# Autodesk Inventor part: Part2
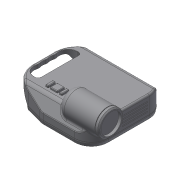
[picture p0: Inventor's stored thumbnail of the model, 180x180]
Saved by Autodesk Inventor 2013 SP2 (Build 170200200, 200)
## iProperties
Created: 2013-06
Part Number: Part2
Material: 一般
Document SubType Name: Modeling
Designer: 3214325
Density: 1 g/cm^3
Author: 3214325
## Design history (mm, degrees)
sketch "Sketch1"
  geometry: L1 (66, -150)-(-66, -150); L2 (-66, -150)-(-66, 0); L3 (-66, 0)-(66, 0); L4 (66, 0)-(66, -150); L5 (92.4, 0)-(-92.4, 0) reference; L6 (0, -180)-(0, 30) reference; 1 further point
  constraints: 8 end point, 2 parallel, 1 collinear, 1 horizontal, 1 perpendicular, 1 other
  dimensions: "d0" = 132 distance of L2.end L3.end; "d1" = 150 distance of L1.end L2.end
extrude "Extrusion1" new body sketch "Sketch1" distance "d2" = 2; taper "d3" = 0 deg
sketch "Sketch2"
  geometry: L1 (66, -150)-(-66, -150) reference; L2 (66, 0)-(66, -150) reference; L3 (-66, 0)-(66, 0) reference; L4 (-66, -150)-(-66, 0) reference; L5 (92.4, 0)-(-92.4, 0) reference; L6 (-66, -88)-(-49.387, -150); L7 (0, -180)-(0, 30) reference; L8 (66, -88)-(49.387, -150); L9 (-66, -88)-(-66, -150); L10 (-66, -150)-(-49.387, -150); L11 (49.387, -150)-(66, -150); L12 (66, -150)-(66, -88); 1 further point
  constraints: 12 end point, 4 point on line, 2 horizontal, 2 vertical
  dimensions: "d4" = 88 distance from line of L6.start L5; "d5" = 15 deg angle of L6 L4; "d7" = 88 distance from line of L8.start L5; "d8" = 15 deg angle of L8 L2
extrude "Extrusion2" cut sketch "Sketch2" distance "d9" = 2; taper "d10" = 0 deg
fillet "Fillet1" dims "d11" = 30
fillet "Fillet2" dims "d12" = 30
fillet "Fillet3" dims "d13" = 40
sketch "Sketch3"
  geometry: L1 (-18.694, -150)-(18.694, -150) reference; L2 (57.331, -120.353)-(64.978, -91.815) reference; L3 (66, -84.05)-(66, -30) reference; L4 (36, 0)-(-36, 0) reference; L5 (-66, -30)-(-66, -84.05) reference; L6 (-64.978, -91.815)-(-57.331, -120.353) reference; A1 r 40 centre (-18.694, -110) between (-57.331, -120.353) and (-18.694, -150) reference; A2 r 40 centre (18.694, -110) between (18.694, -150) and (57.331, -120.353) reference; A3 r 30 centre (36, -84.05) between (64.978, -91.815) and (66, -84.05) reference; A4 r 30 centre (36, -30) between (66, -30) and (36, 0) reference; A5 r 30 centre (-36, -30) between (-36, 0) and (-66, -30) reference; A6 r 30 centre (-36, -84.05) between (-66, -84.05) and (-64.978, -91.815) reference; 1 further point
extrude "Extrusion3" join sketch "Sketch3" distance "d14" = 5; taper "d15" = -10 deg
sketch "Sketch4"
  geometry: L1 (-18.694, 150)-(18.694, 150) reference; L2 (-27, 145)-(27, 145); L3 (33, 139)-(33, 128); L4 (27, 122)-(-27, 122); L5 (-33, 128)-(-33, 139); L6 (0, 180)-(0, -30) reference; A1 r 6 centre (-27, 139) between (-27, 145) and (-33, 139); A2 r 6 centre (-27, 128) between (-33, 128) and (-27, 122); A3 r 6 centre (27, 128) between (27, 122) and (33, 128); A4 r 6 centre (27, 139) between (33, 139) and (27, 145); 4 further points
  constraints: 8 end point, 8 point on circle, 8 tangent, 6 point on line, 4 centre point, 3 equal radius, 2 parallel, 1 horizontal, 1 perpendicular, 1 other
  dimensions: "d16" = 66 distance of point (33, 122) point (-33, 122); "d17" = 23 distance of point (33, 145) point (33, 122); "d18" = 5 distance between parallel lines of L2 L1; "d19" = 6 radius of A1
extrude "Extrusion4" cut sketch "Sketch4" distance "d20" = 15; taper "d21" = 0 deg
sketch "Sketch5"
  geometry: L1 (-33, 128)-(-33, 139) reference; L2 (-27, 145)-(27, 145) reference; L3 (33, 139)-(33, 128) reference; L4 (27, 122)-(-27, 122) reference; L5 (-57.331, 120.353)-(-64.978, 91.815) reference; L6 (-66, 30)-(-66, 84.05) reference; L7 (36, 0)-(-36, 0) reference; L8 (66, 84.05)-(66, 30) reference; L9 (64.978, 91.815)-(57.331, 120.353) reference; L10 (-18.694, 150)-(18.694, 150) reference; L11 (56.365, 120.094)-(64.012, 91.556); L12 (65, 84.05)-(65, 30); L13 (36, 1)-(-36, 1); L14 (-65, 30)-(-65, 84.05); L15 (-64.012, 91.556)-(-56.365, 120.094); L16 (-18.694, 149)-(18.694, 149); A1 r 6 centre (-27, 128) between (-33, 128) and (-27, 122) reference; A2 r 6 centre (-27, 139) between (-27, 145) and (-33, 139) reference; A3 r 6 centre (27, 139) between (33, 139) and (27, 145) reference; A4 r 6 centre (27, 128) between (27, 122) and (33, 128) reference; A5 r 40 centre (-18.694, 110) between (-18.694, 150) and (-57.331, 120.353) reference; A6 r 30 centre (-36, 84.05) between (-64.978, 91.815) and (-66, 84.05) reference; A7 r 30 centre (-36, 30) between (-66, 30) and (-36, 0) reference; A8 r 30 centre (36, 30) between (36, 0) and (66, 30) reference; A9 r 30 centre (36, 84.05) between (66, 84.05) and (64.978, 91.815) reference; A10 r 40 centre (18.694, 110) between (57.331, 120.353) and (18.694, 150) reference; A11 r 39 centre (18.694, 110) between (56.365, 120.094) and (18.694, 149); A12 r 29 centre (36, 84.05) between (65, 84.05) and (64.012, 91.556); A13 r 29 centre (36, 30) between (36, 1) and (65, 30); A14 r 29 centre (-36, 30) between (-65, 30) and (-36, 1); A15 r 29 centre (-36, 84.05) between (-64.012, 91.556) and (-65, 84.05); A16 r 39 centre (-18.694, 110) between (-18.694, 149) and (-56.365, 120.094); 1 further point
  constraints: 12 end point, 12 point on circle, 6 centre point, 11 other
  dimensions: "d28" = 1 distance between parallel lines of L8 L12
extrude "Extrusion5" join sketch "Sketch5" distance "d22" = 0.3; taper "d23" = 0 deg
sketch "Sketch6"
  geometry: L1 (-33, 128)-(-33, 139) reference; L2 (-27, 145)-(27, 145) reference; L3 (33, 139)-(33, 128) reference; L4 (27, 122)-(-27, 122) reference; L5 (18.694, 149)-(-18.694, 149) reference; L6 (-56.365, 120.094)-(-64.012, 91.556) reference; L7 (-65, 84.05)-(-65, 30) reference; L8 (-36, 1)-(36, 1) reference; L9 (65, 30)-(65, 84.05) reference; L10 (64.012, 91.556)-(56.365, 120.094) reference; L11 (0, 206.201)-(0, -40.207) reference; L12 (-99.409, 0)-(99.409, 0) reference; L13 (-39, 171)-(39, 171); L14 (39, 171)-(39, 121); L15 (39, 121)-(-39, 121); L16 (-39, 121)-(-39, 171); A1 r 6 centre (-27, 139) between (-27, 145) and (-33, 139) reference; A2 r 6 centre (27, 139) between (33, 139) and (27, 145) reference; A3 r 6 centre (27, 128) between (27, 122) and (33, 128) reference; A4 r 6 centre (-27, 128) between (-33, 128) and (-27, 122) reference; A5 r 39 centre (18.694, 110) between (56.365, 120.094) and (18.694, 149) reference; A6 r 39 centre (-18.694, 110) between (-18.694, 149) and (-56.365, 120.094) reference; A7 r 29 centre (-36, 84.05) between (-64.012, 91.556) and (-65, 84.05) reference; A8 r 29 centre (-36, 30) between (-65, 30) and (-36, 1) reference; A9 r 29 centre (36, 30) between (36, 1) and (65, 30) reference; A10 r 29 centre (36, 84.05) between (65, 84.05) and (64.012, 91.556) reference
  constraints: 8 end point, 2 parallel, 1 horizontal, 1 perpendicular, 1 other
  dimensions: "d29" = 78 distance of L14.end L15.end; "d30" = 50 distance of L13.end L14.end; "d31" = 121 distance between parallel lines of L12 L15
extrude "Extrusion6" cut sketch "Sketch6" stored distance "d32" = 0.3; taper "d33" = 0 deg
fillet "Fillet4" dims "d34" = 6
fillet "Fillet5" dims "d35" = 2
sketch "Sketch7"
  geometry: L1 (-56.365, 120.094)-(-64.012, 91.556) reference; L2 (-65, 84.05)-(-65, 30) reference; L3 (-36, 1)-(36, 1) reference; L4 (65, 30)-(65, 84.05) reference; L5 (64.012, 91.556)-(56.365, 120.094) reference; L6 (39, 143.297)-(39, 121) reference; L7 (39, 121)-(-39, 121) reference; L8 (-39, 121)-(-39, 143.297) reference; L9 (66, 84.05)-(66, 30); L10 (36, 0)-(-36, 0); L11 (-66, 30)-(-66, 84.05); L12 (-64.978, 91.815)-(-57.331, 120.353); L13 (-38, 139.52)-(-38, 127); L14 (-33, 122)-(33, 122); L15 (38, 127)-(38, 139.52); L16 (57.331, 120.353)-(64.978, 91.815); A1 r 2 centre (-41, 139.52) between (-39, 139.52) and (-42.206, 141.116) reference; A2 r 39 centre (-18.694, 110) between (-39, 143.297) and (-56.365, 120.094) reference; A3 r 29 centre (-36, 84.05) between (-64.012, 91.556) and (-65, 84.05) reference; A4 r 29 centre (-36, 30) between (-65, 30) and (-36, 1) reference; A5 r 29 centre (36, 30) between (36, 1) and (65, 30) reference; A6 r 29 centre (36, 84.05) between (65, 84.05) and (64.012, 91.556) reference; A7 r 39 centre (18.694, 110) between (56.365, 120.094) and (39, 143.297) reference; A8 r 2 centre (41, 139.52) between (42.206, 141.116) and (39, 139.52) reference; A9 r 6 centre (33, 127) between (33, 121) and (39, 127) reference; A10 r 6 centre (-33, 127) between (-39, 127) and (-33, 121) reference; A11 r 30 centre (36, 30) between (36, 0) and (66, 30); A12 r 30 centre (-36, 30) between (-66, 30) and (-36, 0); A13 r 30 centre (-36, 84.05) between (-64.978, 91.815) and (-66, 84.05); A14 r 40 centre (-18.694, 110) between (-42.809, 141.914) and (-57.331, 120.353); A15 r 3 centre (-41, 139.52) between (-38, 139.52) and (-42.809, 141.914); A16 r 5 centre (-33, 127) between (-38, 127) and (-33, 122); A17 r 5 centre (33, 127) between (33, 122) and (38, 127); A18 r 3 centre (41, 139.52) between (42.809, 141.914) and (38, 139.52); A19 r 40 centre (18.694, 110) between (57.331, 120.353) and (42.809, 141.914); A20 r 30 centre (36, 84.05) between (66, 84.05) and (64.978, 91.815); 1 further point
  constraints: 20 point on circle, 16 end point, 10 centre point, 17 other
  dimensions: "d36" = 1 distance between parallel lines of L4 L9
extrude "Extrusion7" join sketch "Sketch7" distance "d37" = 30.7; taper "d38" = 0 deg
sketch "Sketch8"
  geometry: L1 (66, 31)-(64.978, 31) reference; L2 (64.978, 31)-(57.331, 31) reference; L3 (57.331, 31)-(42.809, 31) reference; L4 (42.809, 31)-(38, 31) reference; L5 (38, 31)-(33, 31) reference; L6 (33, 31)-(-33, 31) reference; L7 (-33, 31)-(-38, 31) reference; L8 (-38, 31)-(-42.809, 31) reference; L9 (-42.809, 31)-(-57.331, 31) reference; L10 (-57.331, 31)-(-64.978, 31) reference; L11 (-64.978, 31)-(-66, 31) reference; L12 (-66, 31)-(-36, 31) reference; L13 (-36, 31)-(36, 31) reference; L14 (36, 31)-(66, 31) reference; L15 (-66, 0.3)-(-66, 31) reference; L16 (-66, 0.3)-(-66, 31) reference; L17 (66, 0.3)-(66, 31) reference; L18 (66, 0.3)-(66, 31) reference; L19 (-66, 31)-(-66, 11.006); L20 (-66, 11.006)-(-52, 31); L21 (-52, 31)-(-66, 31); L22 (66, 31)-(66, 11.006); L23 (66, 11.006)-(52, 31); L24 (52, 31)-(66, 31); 1 further point
  constraints: 12 end point, 4 point on line, 2 horizontal
  dimensions: "d39" = 14 distance from line of L20.end L15; "d40" = 14 distance from line of L23.end L17; "d41" = 55 deg angle of L6 L20; "d42" = 55 deg angle of L6 L23
extrude "Extrusion8" cut sketch "Sketch8" distance "d43" = 200; taper "d44" = 0 deg; dims "d52" = 10, "d108" = 1, "d154" = 5, "d193" = 0.5
sketch "Sketch9"
  geometry: L1 (-8.6, 0)-(37.6, 0) reference; L2 (0, -180)-(0, 30) reference; L3 (0, -150)-(-2, -150) reference; L4 (31, -132.152)-(31, -4.623) reference; L5 (31, -116)-(0.386, -150); L6 (0.386, -150)-(31, -150); L7 (31, -150)-(31, -116); L8 (6, -143.765)-(6, -150); 1 further point
  constraints: 8 end point, 3 point on line, 2 vertical, 1 collinear, 1 horizontal
  dimensions: "d45" = 34 distance from line of L5.start L6; "d47" = 42 deg angle of L5 L7; "d51" = 25 distance between parallel lines of L7 L8
extrude "Extrusion9" cut sketch "Sketch9" stored distance "d49" = 200; taper "d50" = 0 deg
fillet "Fillet6" dims "d52" = 10
fillet "Fillet7" dims "d53" = 8
fillet "Fillet8" dims "d54" = 3
sketch "Sketch10"
  geometry: L1 (-66, 0.3)-(-66, 11.006) reference; L2 (-66, 0.3)-(-66, 11.006) reference; L3 (66, 0.3)-(36, 0.3) reference; L4 (36, 0.3)-(-36, 0.3) reference; L5 (-36, 0.3)-(-66, 0.3) reference; L6 (-66, 0.3)-(-64.978, 0.3) reference; L7 (-64.978, 0.3)-(-57.331, 0.3) reference; L8 (-57.331, 0.3)-(-42.809, 0.3) reference; L9 (-42.809, 0.3)-(-40.334, 0.3) reference; L10 (-38, 0.3)-(-33, 0.3) reference; L11 (-33, 0.3)-(33, 0.3) reference; L12 (33, 0.3)-(38, 0.3) reference; L13 (38, 0.3)-(39, 0.3) reference; L14 (42.809, 0.3)-(57.331, 0.3) reference; L15 (57.331, 0.3)-(64.978, 0.3) reference; L16 (64.978, 0.3)-(66, 0.3) reference; L17 (64.012, 0.3)-(56.365, 0.3) reference; L18 (56.365, 0.3)-(40.334, 0.3) reference; L19 (39, 0.3)-(-39, 0.3) reference; L20 (-40.334, 0.3)-(-56.365, 0.3) reference; L21 (-56.365, 0.3)-(-64.012, 0.3) reference; L22 (-64.012, 0.3)-(-65, 0.3) reference; L23 (-65, 0.3)-(-36, 0.3) reference; L24 (-36, 0.3)-(36, 0.3) reference; L25 (36, 0.3)-(65, 0.3) reference; L26 (65, 0.3)-(64.012, 0.3) reference; L27 (-39, 0.3)-(-38, 0.3) reference; L28 (40.334, 0.3)-(42.809, 0.3) reference; C1 r 22 at (-44, 33); 1 further point
  constraints: 1 centre point
  dimensions: "d55" = 44 diameter of C1; "d56" = 22 distance from line of C1.centre L1; "d57" = 32.7 distance from line of C1.centre L19
extrude "Extrusion10" new body sketch "Sketch10" distance "d58" = 60; taper "d59" = 0 deg
sketch "Sketch11"
  geometry: C1 r 22 at (0, 0) reference; 1 further point
extrude "Extrusion11" join sketch "Sketch11" distance "d60" = 6; taper "d61" = 0 deg
sketch "Sketch12"
  geometry: C1 r 22 at (0, 0) reference; C2 r 21 at (0, 0); 1 further point
  constraints: 1 centre point
  dimensions: "d62" = 1 radial gap between concentric circles of C1 C2
extrude "Extrusion12" join sketch "Sketch12" distance "d63" = 1; taper "d64" = 0 deg
sketch "Sketch13"
  geometry: C1 r 21 at (0, 0) reference; C2 r 22 at (0, 0); 1 further point
  constraints: 1 centre point
  dimensions: "d65" = 44 diameter of C2
extrude "Extrusion13" join sketch "Sketch13" distance "d67" = 6; taper "d68" = 0 deg
sketch "Sketch14"
  geometry: C1 r 22 at (0, 0) reference; C2 r 18 at (0, 0); 1 further point
  constraints: 1 centre point
  dimensions: "d69" = 36 diameter of C2
extrude "Extrusion14" cut sketch "Sketch14" distance "d71" = 5; taper "d72" = 0 deg
fillet "Fillet9" dims "d73" = 12
chamfer "Chamfer1" distance "d74" = 2; stored, may be unused: second distance "d75" = 2, angle "d76" = 45 deg
combine "Combine1"
  body "Solid2"
fillet "Fillet10" dims "d77" = 6
sketch "Sketch15"
  geometry: L1 (-42, 104)-(-31, 104); L2 (-30, 103)-(-30, 100); L3 (-31, 99)-(-42, 99); L4 (-43, 100)-(-43, 103); L5 (-42, 80)-(-31, 80); L6 (-30, 79)-(-30, 76); L7 (-31, 75)-(-42, 75); L8 (-43, 76)-(-43, 79); L9 (-92.4, 0)-(92.4, 0) reference; L10 (0, 180)-(0, -30) reference; L11 (-66, 30)-(-66, 84.05) reference; L12 (-36.5, 104)-(-36.5, 75); L13 (-31, 104.25)-(-42, 104.25); L14 (-43.25, 103)-(-43.25, 100); L15 (-42, 98.75)-(-31, 98.75); L16 (-29.75, 100)-(-29.75, 103); L17 (-31, 80.25)-(-42, 80.25); L18 (-43.25, 79)-(-43.25, 76); L19 (-42, 74.75)-(-31, 74.75); L20 (-29.75, 76)-(-29.75, 79); L21 (-66, 30)-(-66, 84.05) reference; A1 r 1 centre (-42, 103) between (-42, 104) and (-43, 103); A2 r 1 centre (-42, 100) between (-43, 100) and (-42, 99); A3 r 1 centre (-31, 103) between (-30, 103) and (-31, 104); A4 r 1 centre (-31, 100) between (-31, 99) and (-30, 100); A5 r 1 centre (-42, 79) between (-42, 80) and (-43, 79); A6 r 1 centre (-31, 79) between (-30, 79) and (-31, 80); A7 r 1 centre (-31, 76) between (-31, 75) and (-30, 76); A8 r 1 centre (-42, 76) between (-43, 76) and (-42, 75); A9 r 1.25 centre (-42, 103) between (-42, 104.25) and (-43.25, 103); A10 r 1.25 centre (-42, 100) between (-43.25, 100) and (-42, 98.75); A11 r 1.25 centre (-31, 100) between (-31, 98.75) and (-29.75, 100); A12 r 1.25 centre (-31, 103) between (-29.75, 103) and (-31, 104.25); A13 r 1.25 centre (-42, 79) between (-42, 80.25) and (-43.25, 79); A14 r 1.25 centre (-42, 76) between (-43.25, 76) and (-42, 74.75); A15 r 1.25 centre (-31, 76) between (-31, 74.75) and (-29.75, 76); A16 r 1.25 centre (-31, 79) between (-29.75, 79) and (-31, 80.25); 6 further points
  constraints: 34 end point, 32 point on circle, 16 centre point, 16 tangent, 10 point on line, 8 parallel, 6 equal radius, 4 perpendicular, 2 horizontal, 2 midpoint, 1 collinear, 14 other
  dimensions: "d78" = 13 distance of point (-30, 99) point (-43, 99); "d79" = 5 distance of point (-30, 104) point (-30, 99); "d80" = 5 distance of point (-30, 80) point (-30, 75); "d81" = 104 distance between parallel lines of L1 L9; "d82" = 19 distance between parallel lines of L5 L3; "d84" = 1 radius of A1; "d85" = 1 radius of A5; "d86" = 0.25 distance between parallel lines of L16 L2; "d87" = 0.25 distance between parallel lines of L20 L6
extrude "Extrusion15" cut sketch "Sketch15" distance "d88" = 5; taper "d89" = 0 deg
extrude "Extrusion16" join sketch "Sketch15" distance "d90" = 3; taper "d92" = 0 deg; dims "d91" = 5, "d93" = 0
extrude "Extrusion17" join sketch "Sketch15" distance "d94" = 3; taper "d96" = 0 deg; dims "d95" = 5, "d97" = 0
fillet "Fillet11" dims "d98" = 1
sketch "Sketch16"
  geometry: L1 (-92.4, 0)-(92.4, 0) reference; L2 (0, -180)-(0, 30) reference; C1 r 7.5 at (-41, -27.5); C2 r 7.5 at (41, -27.5); C3 r 7.5 at (-41, -112.5); C4 r 7.5 at (41, -112.5); 1 further point
  constraints: 4 centre point, 2 horizontal alignment, 2 vertical alignment, 1 symmetric about line
  dimensions: "d99" = 15 diameter of C1; "d100" = 15 diameter of C2; "d101" = 15 diameter of C3; "d102" = 15 diameter of C4; "d103" = 20 distance edge to line of C1 L1; "d104" = 100 dimension on C3 C1; "d105" = 97 dimension on C2 C1
extrude "Extrusion18" join sketch "Sketch16" distance "d106" = 5; taper "d107" = 0 deg
fillet "Fillet12" dims "d108" = 1
sketch "Sketch17"
  geometry: L1 (72, 0)-(0, 0) reference; L2 (25, 7)-(68, 7); L3 (69, 6)-(69, 6); L4 (68, 5)-(25, 5); L5 (24, 6)-(24, 6); L6 (46.5, 5)-(46.5, 7); C1 r 18 at (-8, 32.7) reference; A1 r 1 centre (25, 6) between (25, 7) and (24, 6); A2 r 1 centre (25, 6) between (24, 6) and (25, 5); A3 r 1 centre (68, 6) between (68, 5) and (69, 6); A4 r 1 centre (68, 6) between (69, 6) and (68, 7); 4 further points
  constraints: 10 end point, 8 point on circle, 8 tangent, 6 point on line, 4 centre point, 3 equal radius, 2 midpoint, 2 parallel, 1 horizontal, 1 perpendicular
  dimensions: "d109" = 45 distance of point (69, 5) point (24, 5); "d110" = 2 distance of point (69, 7) point (69, 5); "d111" = 1 radius of A1; "d113" = 5 distance between parallel lines of L4 L1; "d119" = 54.5 horizontal distance of C1.centre L6.start
extrude "Extrusion19" join sketch "Sketch17" distance "d114" = 0.1; taper "d115" = 0 deg
pattern_linear "Rectangular Pattern1" dims "d118" = 5
sketch "Sketch19"
  geometry: L1 (-57.331, 120.353)-(-64.978, 91.815) reference; L2 (-18.694, 150)-(18.694, 150) reference; L3 (64.978, 91.815)-(57.331, 120.353) reference; L4 (-66, 84.05)-(66, 84.05); L5 (-33, 139)-(-33, 128) reference; L6 (-27, 122)-(27, 122) reference; L7 (33, 128)-(33, 139) reference; L8 (27, 145)-(-27, 145) reference; A1 r 30 centre (-36, 84.05) between (-64.978, 91.815) and (-66, 84.05) reference; A2 r 40 centre (-18.694, 110) between (-18.694, 150) and (-57.331, 120.353) reference; A3 r 40 centre (18.694, 110) between (57.331, 120.353) and (18.694, 150) reference; A4 r 30 centre (36, 84.05) between (66, 84.05) and (64.978, 91.815) reference; A5 r 6 centre (-27, 139) between (-27, 145) and (-33, 139) reference; A6 r 6 centre (-27, 128) between (-33, 128) and (-27, 122) reference; A7 r 6 centre (27, 128) between (27, 122) and (33, 128) reference; A8 r 6 centre (27, 139) between (33, 139) and (27, 145) reference; 1 further point
  constraints: 2 end point, 1 parallel
extrude "Extrusion20" join sketch "Sketch19" distance "d120" = 7; taper "d121" = 0 deg
delete_face "Delete Face1"
delete_face "Delete Face2"
sketch "Sketch20"
  geometry: L1 (6, 23.7)-(0, 23.7) reference; L2 (-41.343, -60.416)-(107.343, -60.416); L3 (107.343, -60.416)-(107.343, 23.7); L4 (107.343, 23.7)-(-41.343, 23.7); L5 (-41.343, 23.7)-(-41.343, -60.416); L6 (-41.343, -60.416)-(107.343, 23.7); L7 (107.343, -60.416)-(-41.343, 23.7); L8 (-6, -0.3)-(72, -0.3) reference; 4 further points
  constraints: 12 end point, 4 midpoint, 2 parallel, 1 collinear, 1 horizontal, 1 perpendicular, 1 vertical alignment
extrude "Extrusion21" cut sketch "Sketch20" distance "d122" = 55.75; taper "d123" = 0 deg
delete_face "Delete Face3"
delete_face "Delete Face4"
chamfer "Chamfer2" distance "d124" = 23; stored, may be unused: second distance "d125" = 2, angle "d126" = 45 deg
sketch "Sketch21"
  geometry: L1 (1, -122)-(0.3, -122) reference; L2 (1, -122)-(7, -128) reference; L3 (7, -128)-(18, -139) reference; L4 (24, -145)-(18, -139) reference; L5 (24, -150)-(24, -145) reference; L6 (0.3, -122)-(24, -145.7); 1 further point
  constraints: 2 end point, 1 parallel, 1 point on line
extrude "Extrusion22" join sketch "Sketch21" stored distance "d127" = 125.25; taper "d128" = 0 deg
delete_face "Delete Face5"
delete_face "Delete Face6"
delete_face "Delete Face7"
delete_face "Delete Face8"
fillet "Fillet13" dims "d129" = 16
feature "Move Face1"
feature "Move Face2"
sketch "Sketch23"
  geometry: L1 (56.694, -21)-(56.694, -22) reference; L2 (50.694, -28)-(-13.306, -28) reference; L3 (-19.306, -22)-(-19.306, -21) reference; L4 (-3.306, -5)-(40.694, -5) reference; L5 (70.694, -145.377)-(70.694, -17.848) reference; L6 (-3.306, -5)-(40.694, -5); A1 r 6 centre (50.694, -22) between (50.694, -28) and (56.694, -22) reference; A2 r 6 centre (-13.306, -22) between (-19.306, -22) and (-13.306, -28) reference; A3 r 16 centre (-3.306, -21) between (-3.306, -5) and (-19.306, -21) reference; A4 r 16 centre (40.694, -21) between (56.694, -21) and (40.694, -5) reference; A5 r 16 centre (25.694, -21) between (33.194, -6.867) and (18.694, -6.613); A6 r 16 centre (11.694, -21) between (18.694, -6.613) and (4.194, -6.867); A7 r 16 centre (40.694, -21) between (56.682, -21.62) and (56.694, -21); A8 r 16 centre (40.694, -21) between (40.694, -5) and (33.194, -6.867); A9 r 16 centre (-3.306, -21) between (4.194, -6.867) and (-3.306, -5); A10 r 16 centre (-3.306, -21) between (-19.306, -21) and (-19.1, -23.558); 3 further points
  constraints: 15 point on circle, 6 centre point, 6 tangent, 4 end point, 2 coincident, 2 midpoint, 1 horizontal alignment, 1 perpendicular, 1 vertical alignment
  dimensions: "d145" = 16 radius of A6; "d195" = 15 distance of A9.centre A6.centre
extrude "Extrusion24" join sketch "Sketch23" stored distance "d147" = 125.25; taper "d148" = 0 deg
fillet "Fillet14" dims "d149" = 10
sketch "Sketch24"
  geometry: L1 (0.3, -120.353)-(0.3, -122) reference; L2 (24, -150)-(24, -145.7) reference; L3 (0.3, -122)-(24, -141.887); L4 (24, -141.887)-(24, -150); L5 (0.3, -122)-(24, -150); L6 (31, -122)-(0.3, -122) reference; 1 further point
  constraints: 6 end point, 1 collinear
  dimensions: "d150" = 40 deg angle of L3 L6
extrude "Extrusion25" cut sketch "Sketch24" stored distance "d151" = 125.25; taper "d152" = 0 deg
fillet "Fillet15" dims "d153" = 5
delete_face "Delete Face9"
fillet "Fillet16" dims "d154" = 5
sketch "Sketch25"
  geometry: L1 (-11.306, -50)-(-11.306, -47) reference; L2 (-23.306, -51)-(-12.306, -51) reference; L3 (-24.306, -47)-(-24.306, -50) reference; L4 (-23.306, -67)-(-12.306, -67); L5 (-11.306, -66)-(-11.306, -55); L6 (-12.306, -54)-(-23.306, -54); L7 (-24.306, -55)-(-24.306, -66); L8 (-23.306, -70)-(-12.306, -70) reference; A1 r 1 centre (-12.306, -55) between (-11.306, -55) and (-12.306, -54); A2 r 1 centre (-23.306, -55) between (-23.306, -54) and (-24.306, -55); A3 r 1 centre (-23.306, -66) between (-24.306, -66) and (-23.306, -67); A4 r 1 centre (-12.306, -66) between (-12.306, -67) and (-11.306, -66); 1 further point
  constraints: 8 end point, 8 point on circle, 8 tangent, 4 centre point, 3 equal radius, 2 collinear, 2 parallel, 1 horizontal, 1 perpendicular
  dimensions: "d157" = 3 distance between parallel lines of L4 L8; "d158" = 3 distance between parallel lines of L2 L6 (derived); "d159" = 1 radius of A1
extrude "Extrusion26" join sketch "Sketch25" stored distance "d160" = 125.25; taper "d161" = 0 deg
sketch "Sketch26"
  geometry: L1 (-24.306, -66)-(-24.306, -55) reference; L2 (-23.306, -54)-(-12.306, -54) reference; L3 (-11.306, -55)-(-11.306, -66) reference; L4 (-12.306, -67)-(-23.306, -67) reference; L5 (-12.306, -46)-(-23.306, -46) reference; L6 (-11.306, -50)-(-11.306, -47) reference; L7 (-23.306, -51)-(-12.306, -51) reference; L8 (-24.306, -47)-(-24.306, -50) reference; L9 (-11.056, -66)-(-11.056, -55); L10 (-12.306, -53.75)-(-23.306, -53.75); L11 (-24.556, -55)-(-24.556, -66); L12 (-23.306, -67.25)-(-12.306, -67.25); L13 (-12.306, -45.75)-(-23.306, -45.75); L14 (-24.556, -47)-(-24.556, -50); L15 (-23.306, -51.25)-(-12.306, -51.25); L16 (-11.056, -50)-(-11.056, -47); A1 r 1 centre (-23.306, -55) between (-23.306, -54) and (-24.306, -55) reference; A2 r 1 centre (-12.306, -55) between (-11.306, -55) and (-12.306, -54) reference; A3 r 1 centre (-12.306, -66) between (-12.306, -67) and (-11.306, -66) reference; A4 r 1 centre (-23.306, -66) between (-24.306, -66) and (-23.306, -67) reference; A5 r 1 centre (-23.306, -47) between (-23.306, -46) and (-24.306, -47) reference; A6 r 1 centre (-12.306, -47) between (-11.306, -47) and (-12.306, -46) reference; A7 r 1 centre (-12.306, -50) between (-12.306, -51) and (-11.306, -50) reference; A8 r 1 centre (-23.306, -50) between (-24.306, -50) and (-23.306, -51) reference; A9 r 1.25 centre (-12.306, -55) between (-11.056, -55) and (-12.306, -53.75); A10 r 1.25 centre (-23.306, -55) between (-23.306, -53.75) and (-24.556, -55); A11 r 1.25 centre (-23.306, -66) between (-24.556, -66) and (-23.306, -67.25); A12 r 1.25 centre (-12.306, -66) between (-12.306, -67.25) and (-11.056, -66); A13 r 1.25 centre (-12.306, -47) between (-11.056, -47) and (-12.306, -45.75); A14 r 1.25 centre (-23.306, -47) between (-23.306, -45.75) and (-24.556, -47); A15 r 1.25 centre (-23.306, -50) between (-24.556, -50) and (-23.306, -51.25); A16 r 1.25 centre (-12.306, -50) between (-12.306, -51.25) and (-11.056, -50); 1 further point
  constraints: 16 end point, 16 point on circle, 8 centre point, 14 other
  dimensions: "d162" = 0.25 distance between parallel lines of L3 L9; "d163" = 0.25 distance between parallel lines of L6 L16
extrude "Extrusion27" cut sketch "Sketch26" stored distance "d164" = 125.25; taper "d165" = 0 deg
delete_face "Delete Face10"
feature "Move Face3"
sketch "Sketch27"
  geometry: L1 (19.926, 121.118)-(91.926, 121.118) reference; L2 (91.926, 122)-(19.926, 122) reference; C1 r 15 at (55.926, 92); 2 further points
  constraints: 1 centre point, 1 midpoint, 1 vertical alignment
  dimensions: "d166" = 30 diameter of C1; "d170" = 15 distance edge to line of C1 L2
extrude "Extrusion28" join sketch "Sketch27" stored distance "d171" = 125.25; taper "d172" = 0 deg
sketch "Sketch28"
  geometry: L1 (0, 0)-(9.192, 9.192); L2 (0.75, 0)-(22.911, 0); A1 r 15 centre (0, 0) between (13.707, 6.092) and (6.092, 13.707) reference; A2 r 15 centre (19.799, 19.799) between (6.092, 13.707) and (13.707, 6.092); 1 further point
  constraints: 5 point on circle, 4 end point, 1 centre point, 1 horizontal, 1 point on line
  dimensions: "d173" = 45 deg angle of L1 L2; "d174" = 2 dimension on A1 A2; "d175" = 15 radius of A2
extrude "Extrusion29" cut sketch "Sketch28" stored distance "d176" = 125.25; taper "d177" = 0 deg
pattern_circular "Circular Pattern1" dims angle "d179" = 360 deg
fillet "Fillet17" dims "d181" = 8
fillet "Fillet18" dims "d182" = 3
fillet "Fillet19" dims "d183" = 6
fillet "Fillet20" dims "d184" = 0.5
fillet "Fillet23" dims "d187" = 1
fillet "Fillet24" dims "d188" = 1
fillet "Fillet25" dims "d189" = 1
chamfer "Chamfer3" distance "d190" = 5; stored, may be unused: second distance "d191" = 2, angle "d192" = 10 deg
fillet "Fillet26" dims "d193" = 0.5
fillet "Fillet27" dims "d194" = 0.5
body "Solid1"
node "Projected Loop1"
node "Projected Loop2"
node "Projected Loop3"
node "Projected Loop4"
node "Projected Loop5"
node "Projected Loop6"
node "Projected Loop7"
node "Projected Loop8"
node "Projected Loop9"
other parameters: "d142" = 1, "d144" = 16
